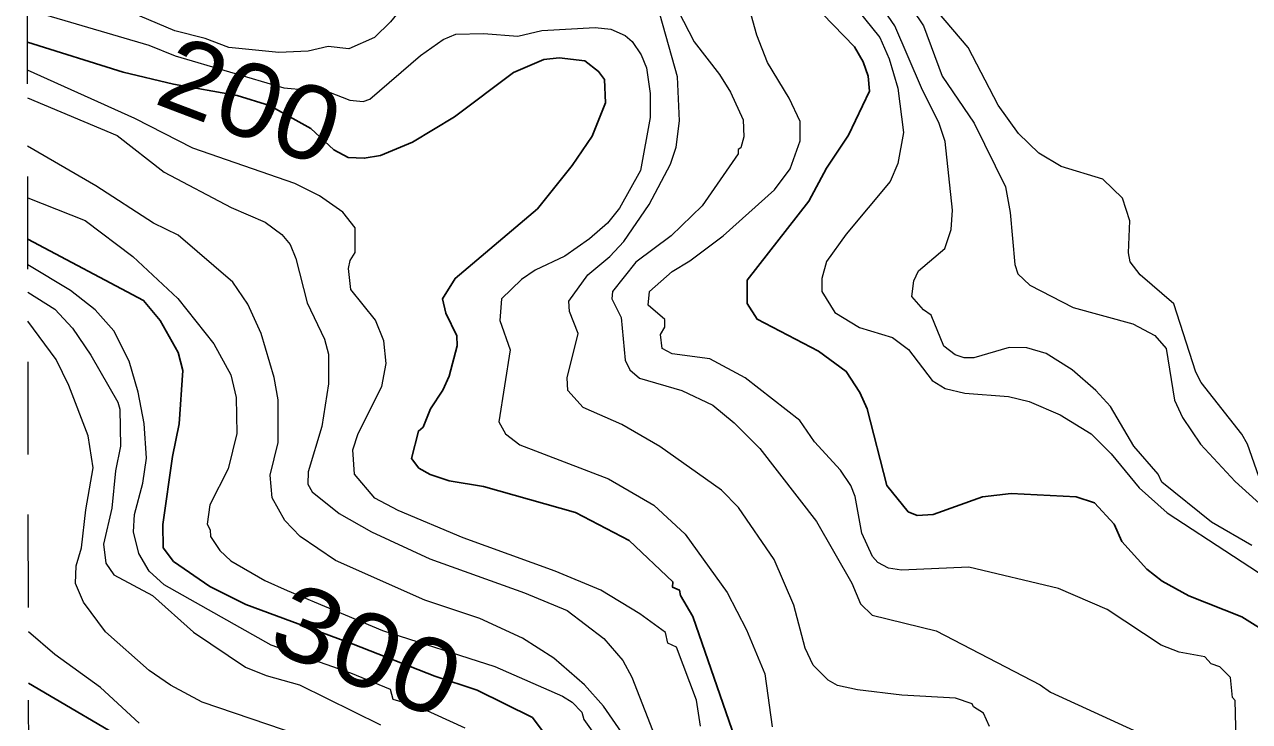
# Model space of a CAD drawing. Extents: x 474.5 to 500, y 7345.7 to 7373.4.
# Drawn here: x 474.522 to 475.844, y 7370.847 to 7371.599 of the extents above; entities that cross this region are included whole.
import ezdxf
from ezdxf.enums import TextEntityAlignment as Align

# ---------------------------------------------------------------- set-up
doc = ezdxf.new("R2010")
doc.units = 0
doc.header["$LTSCALE"] = 0.032
doc.linetypes.add('SHORT_DASHED', pattern=[2.7, 1.5, -1.2])
for name, color, linetype, lineweight in [('1', 7, 'Continuous', 25), ('2', 7, 'Continuous', 13), ('22', 7, 'SHORT_DASHED', 13)]:
    doc.layers.add(name, color=color, linetype=linetype, lineweight=lineweight)
doc.layers.add('61', color=7, linetype='Continuous')

msp = doc.modelspace()

# ---------------------------------------------------------------- linework, layer by layer
at = {"layer": '1'}
for points in [[(475.869, 7370.9388), (475.8356, 7370.9597), (475.7783, 7370.9824), (475.7497, 7370.9983), (475.733, 7371.0111), (475.7062, 7371.041), (475.6979, 7371.0596), (475.6765, 7371.0826), (475.6568, 7371.0891), (475.5868, 7371.0929), (475.5556, 7371.0891), (475.5026, 7371.07), (475.4851, 7371.0692), (475.4756, 7371.0732), (475.4525, 7371.1016), (475.4315, 7371.1843), (475.4235, 7371.2018), (475.4087, 7371.2245), (475.3788, 7371.2464), (475.3127, 7371.2808), (475.3018, 7371.2979), (475.3018, 7371.3231), (475.3685, 7371.4084), (475.3873, 7371.444), (475.4111, 7371.4794), (475.434, 7371.527), (475.4324, 7371.543), (475.4269, 7371.5587), (475.4175, 7371.5747), (475.3715, 7371.6222)], [(475.292, 7370.8186), (475.2434, 7370.9602), (475.23, 7370.9828), (475.2289, 7370.9884), (475.2213, 7370.9918), (475.2216, 7370.9976), (475.1747, 7371.042), (475.1168, 7371.0722), (475.0173, 7371.1003), (474.9803, 7371.1065), (474.9598, 7371.1135), (474.9476, 7371.1203), (474.9396, 7371.1307), (474.9471, 7371.1601), (474.9523, 7371.1643), (474.9603, 7371.1842), (474.9736, 7371.2045), (474.9804, 7371.2195), (474.9889, 7371.2523), (474.9888, 7371.2629), (474.9766, 7371.2874), (474.9731, 7371.3029), (474.9869, 7371.3249), (475.0756, 7371.4), (475.1129, 7371.4466), (475.1345, 7371.4785), (475.1492, 7371.5142), (475.1481, 7371.5395), (475.1415, 7371.5482), (475.1266, 7371.5597), (475.099, 7371.5629), (475.0824, 7371.5611), (475.0499, 7371.547), (474.9862, 7371.4994), (474.9408, 7371.4718), (474.9062, 7371.4577), (474.8887, 7371.4545), (474.8715, 7371.4552), (474.8559, 7371.4637), (474.831, 7371.4868), (474.7864, 7371.5116), (474.7516, 7371.5224), (474.683, 7371.5346), (474.6287, 7371.5476), (474.5254, 7371.5799)], [(475.0862, 7370.8298), (475.0701, 7370.8513), (475.0104, 7370.8805), (474.9648, 7370.8956), (474.8768, 7370.9301), (474.761, 7370.9731), (474.7222, 7370.9925), (474.6828, 7371.0195), (474.6719, 7371.0342), (474.6714, 7371.0592), (474.6817, 7371.1329), (474.6889, 7371.168), (474.6929, 7371.2255), (474.688, 7371.2449), (474.6684, 7371.2795), (474.6506, 7371.3012), (474.5258, 7371.3671)], [(474.6478, 7370.817), (474.5266, 7370.8881)]]:
    msp.add_lwpolyline(points, dxfattribs=at)
at = {"layer": '2'}
for points in [[(475.1755, 7371.6706), (475.1571, 7371.693), (475.1452, 7371.7025), (475.1195, 7371.717), (475.0878, 7371.7232), (475.0637, 7371.7193), (475.0467, 7371.7135), (475.0325, 7371.7), (474.9901, 7371.6734), (474.9381, 7371.6277), (474.917, 7371.6018), (474.8999, 7371.585), (474.8722, 7371.5726), (474.8497, 7371.575), (474.8284, 7371.57), (474.7965, 7371.5686), (474.7425, 7371.5739), (474.7171, 7371.5838), (474.6844, 7371.5921), (474.5978, 7371.6292), (474.5573, 7371.6407), (474.5253, 7371.6564)], [(475.8463, 7371.0366), (475.8029, 7371.0618), (475.7491, 7371.105), (475.7451, 7371.1138), (475.719, 7371.1439), (475.6937, 7371.1868), (475.6782, 7371.2038), (475.6526, 7371.2263), (475.6245, 7371.2439), (475.6037, 7371.2501), (475.5846, 7371.2503), (475.5463, 7371.2392), (475.5359, 7371.2391), (475.5264, 7371.2424), (475.5141, 7371.2517), (475.5002, 7371.2853), (475.4921, 7371.2911), (475.4796, 7371.3055), (475.4818, 7371.3223), (475.4868, 7371.3331), (475.5152, 7371.3571), (475.5219, 7371.3776), (475.5235, 7371.3984), (475.5155, 7371.4726), (475.5089, 7371.4922), (475.4898, 7371.5305), (475.461, 7371.5975), (475.3846, 7371.7089)], [(475.8233, 7370.8942), (475.8119, 7370.9059), (475.8025, 7370.9089), (475.7958, 7370.9167), (475.7681, 7370.9217), (475.7484, 7370.9291), (475.6901, 7370.9678), (475.6378, 7370.9903), (475.5409, 7371.0133), (475.4685, 7371.0102), (475.4545, 7371.0124), (475.4427, 7371.0183), (475.4369, 7371.025), (475.4257, 7371.0499), (475.4182, 7371.0896), (475.4138, 7371.1016), (475.4027, 7371.1181), (475.3744, 7371.1487), (475.3586, 7371.1717), (475.2998, 7371.2177), (475.2617, 7371.2382), (475.2208, 7371.2437), (475.21, 7371.2494), (475.2084, 7371.2643), (475.2129, 7371.2724), (475.2129, 7371.2807), (475.1951, 7371.2962), (475.1966, 7371.3109), (475.2209, 7371.3324), (475.2401, 7371.3437), (475.2761, 7371.3707), (475.3314, 7371.4205), (475.3484, 7371.4433), (475.3591, 7371.4734), (475.3589, 7371.4944), (475.347, 7371.5193), (475.3237, 7371.5579), (475.3124, 7371.5875), (475.2929, 7371.6576)], [(475.3818, 7371.6637), (475.4449, 7371.585), (475.4549, 7371.5619), (475.4643, 7371.5302), (475.4707, 7371.4823), (475.4644, 7371.449), (475.4563, 7371.4295), (475.4087, 7371.3725), (475.3875, 7371.343), (475.3823, 7371.3247), (475.3823, 7371.3109), (475.3966, 7371.288), (475.4232, 7371.2718), (475.4587, 7371.2613), (475.476, 7371.2482), (475.5015, 7371.2146), (475.5155, 7371.2062), (475.5368, 7371.201), (475.5837, 7371.1976), (475.6061, 7371.192), (475.6396, 7371.1778), (475.6729, 7371.1572), (475.6945, 7371.1358), (475.7249, 7371.099), (475.755, 7371.0719), (475.8981, 7370.9783)], [(475.8539, 7371.1113), (475.8416, 7371.146), (475.8355, 7371.1567), (475.7916, 7371.2125), (475.7858, 7371.2239), (475.7622, 7371.2976), (475.7257, 7371.3289), (475.7149, 7371.3429), (475.7133, 7371.3526), (475.7148, 7371.3869), (475.7067, 7371.4115), (475.6855, 7371.4319), (475.6405, 7371.4456), (475.6165, 7371.4602), (475.5946, 7371.4813), (475.5725, 7371.5117), (475.5402, 7371.5742), (475.4906, 7371.6326)], [(474.5448, 7371.6094), (474.6565, 7371.5767), (474.6846, 7371.565), (474.802, 7371.5307), (474.8502, 7371.5261), (474.8732, 7371.5172), (474.8874, 7371.5158), (474.8946, 7371.5183), (474.9494, 7371.5656), (474.974, 7371.5828), (474.9874, 7371.5884), (475.0175, 7371.5893), (475.0546, 7371.5862), (475.0804, 7371.5925), (475.1379, 7371.5956), (475.1548, 7371.594), (475.1703, 7371.5871), (475.1777, 7371.5806), (475.1875, 7371.5662), (475.1932, 7371.5523), (475.1971, 7371.5244), (475.1971, 7371.4984), (475.1868, 7371.4412), (475.1643, 7371.4008), (475.1511, 7371.3845), (475.1317, 7371.3675), (475.1052, 7371.349), (475.0732, 7371.3338), (475.0583, 7371.3239), (475.0368, 7371.3027), (475.0352, 7371.2795), (475.0463, 7371.2478), (475.0338, 7371.17), (475.0413, 7371.1571), (475.0566, 7371.1454), (475.1524, 7371.1086), (475.2011, 7371.0803), (475.2348, 7371.049), (475.2803, 7370.9859), (475.3011, 7370.9457), (475.3208, 7370.8982), (475.3287, 7370.8412)], [(475.5633, 7370.8415), (475.557, 7370.8559), (475.546, 7370.8625), (475.5447, 7370.8657), (475.5266, 7370.872), (475.4686, 7370.8753), (475.4208, 7370.8809), (475.3993, 7370.8858), (475.3892, 7370.8914), (475.3729, 7370.9076), (475.3645, 7370.9258), (475.3523, 7370.9725), (475.331, 7371.0215), (475.2924, 7371.0776), (475.2742, 7371.0966), (475.2078, 7371.1437), (475.1666, 7371.1674), (475.1248, 7371.1855), (475.1084, 7371.204), (475.1078, 7371.2175), (475.1197, 7371.2653), (475.1102, 7371.2891), (475.1094, 7371.3002), (475.1299, 7371.3289), (475.1536, 7371.3487), (475.1688, 7371.3648), (475.1962, 7371.4048), (475.219, 7371.4482), (475.2251, 7371.4667), (475.229, 7371.4949), (475.2267, 7371.5425), (475.2079, 7371.6091)], [(475.2273, 7371.6135), (475.2447, 7371.5803), (475.272, 7371.5449), (475.2839, 7371.5257), (475.2977, 7371.4962), (475.2984, 7371.4778), (475.2952, 7371.4659), (475.2923, 7371.4641), (475.292, 7371.4595), (475.2533, 7371.4031), (475.2199, 7371.371), (475.1817, 7371.3425), (475.1565, 7371.3108), (475.1557, 7371.303), (475.166, 7371.2829), (475.1701, 7371.2366), (475.1754, 7371.2261), (475.1857, 7371.2173), (475.2312, 7371.204), (475.2649, 7371.188), (475.2877, 7371.1692), (475.3156, 7371.1414), (475.3768, 7371.0625), (475.4148, 7370.996), (475.4243, 7370.9737), (475.4368, 7370.9614), (475.5056, 7370.9447), (475.6178, 7370.8863), (475.629, 7370.8783), (475.7407, 7370.8273)], [(475.4803, 7371.6152), (475.4922, 7371.5974), (475.5121, 7371.5433), (475.5467, 7371.4925), (475.5806, 7371.4239), (475.5857, 7371.396), (475.5905, 7371.3401), (475.5939, 7371.3297), (475.6069, 7371.3177), (475.6534, 7371.2937), (475.7178, 7371.2758), (475.7416, 7371.2633), (475.7539, 7371.2493), (475.763, 7371.1937), (475.7714, 7371.1747), (475.791, 7371.1462), (475.8283, 7371.1057), (475.8587, 7371.0783)], [(475.2257, 7370.927), (475.2163, 7370.9313), (475.2137, 7370.943), (475.1862, 7370.9629), (475.1439, 7370.9884), (475.0948, 7371.0091), (474.9956, 7371.0451), (474.9254, 7371.0746), (474.9002, 7371.0879), (474.8784, 7371.1137), (474.8765, 7371.14), (474.8823, 7371.1575), (474.9076, 7371.2082), (474.9123, 7371.2332), (474.9099, 7371.2574), (474.901, 7371.2799), (474.8743, 7371.313), (474.8717, 7371.3355), (474.8734, 7371.3443), (474.8789, 7371.3529), (474.879, 7371.3796), (474.8658, 7371.3964), (474.8403, 7371.4139), (474.8137, 7371.4272), (474.7037, 7371.4656), (474.6414, 7371.4974), (474.5255, 7371.5496)], [(474.5255, 7371.5196), (474.6221, 7371.479), (474.6728, 7371.4395), (474.7453, 7371.4016), (474.7818, 7371.3857), (474.7997, 7371.3723), (474.8087, 7371.3616), (474.8151, 7371.3465), (474.8271, 7371.2984), (474.846, 7371.2593), (474.8501, 7371.243), (474.8501, 7371.2111), (474.843, 7371.1651), (474.8284, 7371.1161), (474.8278, 7371.1029), (474.8324, 7371.0948), (474.8617, 7371.0712), (474.8966, 7371.0513), (474.9596, 7371.0225), (475.0616, 7370.9858), (475.1077, 7370.9666), (475.1472, 7370.9363), (475.1676, 7370.9127), (475.1774, 7370.8947), (475.1996, 7370.8375)], [(475.1696, 7370.8306), (475.1468, 7370.8633), (475.1263, 7370.8863), (475.0932, 7370.9153), (475.0594, 7370.9366), (475.0134, 7370.958), (474.9541, 7370.9778), (474.8577, 7371.0207), (474.8195, 7371.0464), (474.8032, 7371.0636), (474.7895, 7371.088), (474.7871, 7371.1125), (474.7959, 7371.1477), (474.7958, 7371.1938), (474.7917, 7371.2181), (474.7774, 7371.2656), (474.7631, 7371.2973), (474.7468, 7371.3208), (474.6881, 7371.3714), (474.6615, 7371.3845), (474.5991, 7371.4248), (474.5256, 7371.4676)], [(474.5257, 7371.412), (474.5878, 7371.3873), (474.6391, 7371.3487), (474.6875, 7371.3034), (474.7264, 7371.2542), (474.7448, 7371.2207), (474.7504, 7371.1965), (474.7512, 7371.1575), (474.742, 7371.1196), (474.7223, 7371.0806), (474.7192, 7371.0599), (474.7224, 7371.0536), (474.7227, 7371.0464), (474.733, 7371.0314), (474.7449, 7371.02), (474.7814, 7370.9989), (474.8056, 7370.988), (474.9083, 7370.945), (475.0296, 7370.906), (475.1025, 7370.8743), (475.113, 7370.8676), (475.1236, 7370.8569), (475.1258, 7370.8488), (475.1427, 7370.8252)], [(474.6187, 7371.2685), (474.5986, 7371.2911), (474.572, 7371.312), (474.5258, 7371.3396)], [(474.5259, 7371.3102), (474.5549, 7371.2917), (474.5739, 7371.2711), (474.5936, 7371.2422), (474.6229, 7371.1915), (474.6251, 7371.184), (474.6259, 7371.1439), (474.6204, 7371.1173), (474.6163, 7371.0771), (474.6076, 7371.0381), (474.6098, 7371.0177), (474.6184, 7371.005), (474.6602, 7370.9829), (474.7047, 7370.9432), (474.7607, 7370.9056), (474.783, 7370.8965), (474.8188, 7370.8862), (474.9064, 7370.8431)], [(474.8895, 7370.8081), (474.714, 7370.8676), (474.6797, 7370.8861), (474.6567, 7370.902), (474.6096, 7370.9434), (474.5857, 7370.9757), (474.5773, 7370.9957), (474.578, 7371.0147), (474.5837, 7371.0343), (474.5884, 7371.0752), (474.5964, 7371.1205), (474.5909, 7371.1551), (474.57, 7371.2094), (474.5565, 7371.2374), (474.5259, 7371.2788), (474.5259, 7371.2789)], [(474.9975, 7370.8395), (474.948, 7370.8623), (474.9199, 7370.8705), (474.9169, 7370.8812), (474.8744, 7370.8991), (474.7884, 7370.9292), (474.6728, 7370.9943), (474.6567, 7371.0092), (474.6456, 7371.0282), (474.6397, 7371.0513), (474.641, 7371.07), (474.6498, 7371.1039), (474.6538, 7371.1308), (474.6514, 7371.1683), (474.6449, 7371.2021), (474.6353, 7371.2356), (474.6187, 7371.2685)], [(474.6458, 7370.8449), (474.6042, 7370.8834), (474.5549, 7370.919), (474.5265, 7370.9436)], [(475.2514, 7370.8416), (475.2473, 7370.8697), (475.2257, 7370.927)], [(475.8456, 7370.7678), (475.8297, 7370.8125), (475.8282, 7370.8693), (475.8256, 7370.8728), (475.8233, 7370.8942)]]:
    msp.add_lwpolyline(points, dxfattribs=at)
at = {"layer": '22'}
msp.add_lwpolyline([(474.5381, 7364.3565), (474.5371, 7364.9213), (474.5361, 7365.4862), (474.5351, 7366.0511), (474.5341, 7366.616), (474.5331, 7367.1808), (474.5321, 7367.7457), (474.5311, 7368.3105), (474.5301, 7368.8754), (474.5291, 7369.4403), (474.5281, 7370.0051), (474.5272, 7370.57), (474.5262, 7371.1349), (474.5252, 7371.6997), (474.5242, 7372.2646), (474.5232, 7372.8295), (474.5222, 7373.3943)], dxfattribs=at)

# ---------------------------------------------------------------- texts
at = {"layer": '61'}
for s, rotation, width, p in [('200', 339.18, 1.1, (474.7517, 7371.4796)), ('300', 337.479, 1.15, (474.8768, 7370.8868))]:
    msp.add_text(s, height=0.08, rotation=rotation, dxfattribs=dict(at, width=width)).set_placement(p, align=Align.CENTER)

doc.saveas('drawing.dxf')
